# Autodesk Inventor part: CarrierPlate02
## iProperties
Created: 2008-02
Part Number: CarrierPlate02
Document SubType Name: Modeling
Designer: grh
Density: 1 g/cm^3
Author: grh
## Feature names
1. Extrusion1
